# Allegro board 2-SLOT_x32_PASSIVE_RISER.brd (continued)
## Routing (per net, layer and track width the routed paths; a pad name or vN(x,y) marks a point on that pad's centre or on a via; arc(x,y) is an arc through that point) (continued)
GND_K:
  vias: v1(-8.51,332.86) v1(-8.51,322.72) v1(-7.51,332.86) v1(-7.51,322.72) v1(-6.51,332.86) v1(-6.51,322.72) v1(-5.52,332.86) v1(-5.52,322.72) v1(-4.52,332.86) v1(-4.52,322.72) v1(-3.52,332.86) v1(-3.52,322.72) v1(-2.52,332.86) v1(-2.52,327.79) v1(-2.52,322.72) v1(-1.52,332.86) v1(-1.52,327.79) v1(-1.52,322.72) v1(2.8,332.86) v1(2.8,327.79) v1(2.8,322.72) v1(3.79,332.86) v1(3.79,327.79) v1(3.79,322.72) v1(4.79,332.86) v1(4.79,327.79) v1(4.79,322.72) v1(5.79,332.86) v1(5.79,327.79) v1(5.79,322.72) v1(6.79,332.86) v1(6.79,327.79) v1(6.79,322.72) v1(7.79,332.86) v1(7.79,327.79) v1(7.79,322.72) v1(8.79,332.86) v1(8.79,327.79) v1(8.79,322.72) v1(9.78,332.86) v1(9.78,327.79) v1(9.78,322.72) v1(10.78,332.86) v1(10.78,327.79) v1(10.78,322.72) v1(11.78,332.86) v1(11.78,327.79) v1(11.78,322.72) v1(12.78,332.86) v1(12.78,327.79) v1(12.78,322.72) v1(13.78,332.86) v1(13.78,327.79) v1(13.78,322.72) v1(14.77,332.86) v1(14.77,327.79) v1(14.77,322.72) v1(15.77,332.86) v1(15.77,327.79) v1(15.77,322.72) v1(16.77,332.86) v1(16.77,327.79) v1(16.77,322.72) v1(17.77,332.86) v1(17.77,327.79) v1(17.77,322.72) v1(18.77,332.86) v1(18.77,327.79) v1(18.77,322.72) v1(19.77,332.86) v1(19.77,327.79) v1(19.77,322.72) v1(20.76,332.86) v1(20.76,327.79) v1(20.76,322.72) v1(21.76,332.86) v1(21.76,327.79) v1(21.76,322.72) v1(22.76,332.86) v1(22.76,327.79) v1(22.76,322.72) v1(23.76,332.86) v1(23.76,327.79) v1(23.76,322.72) v1(24.76,332.86) v1(24.76,327.79) v1(24.76,322.72) v1(25.76,332.86) v1(25.76,327.79) v1(25.76,322.72) v1(26.75,332.86) v1(26.75,327.79) v1(26.75,322.72) v1(27.75,332.86) v1(27.75,327.79) v1(27.75,322.72) v1(28.75,332.86) v1(28.75,327.79) v1(28.75,322.72) v1(29.75,332.86) v1(29.75,327.79) v1(29.75,322.72) v1(30.75,332.86) v1(30.75,327.79) v1(30.75,322.72) v1(31.74,332.86) v1(31.74,327.79) v1(31.74,322.72) v1(32.74,332.86) v1(32.74,327.79) v1(32.74,322.72) v1(33.74,332.86) v1(33.74,327.79) v1(33.74,322.72) v1(34.74,332.86) v1(34.74,327.79) v1(34.74,322.72) v1(35.74,332.86) v1(35.74,327.79) v1(35.74,322.72) v1(36.74,332.86) v1(36.74,327.79) v1(36.74,322.72) v1(37.73,332.86) v1(37.73,327.79) v1(37.73,322.72) v1(38.73,332.86) v1(38.73,327.79) v1(38.73,322.72) v1(39.73,332.86) v1(39.73,327.79) v1(39.73,322.72) v1(40.73,332.86) v1(40.73,327.79) v1(40.73,322.72) v1(41.73,332.86) v1(41.73,327.79) v1(41.73,322.72) v1(42.73,332.86) v1(42.73,327.79) v1(42.73,322.72) v1(43.72,332.86) v1(43.72,327.79) v1(43.72,322.72) v1(44.72,332.86) v1(44.72,327.79) v1(44.72,322.72) v1(45.72,332.86) v1(45.72,327.79) v1(45.72,322.72) v1(46.72,332.86) v1(46.72,327.79) v1(46.72,322.72) v1(47.72,332.86) v1(47.72,327.79) v1(47.72,322.72) v1(48.71,332.86) v1(48.71,327.79) v1(48.71,322.72) v1(49.71,332.86) v1(49.71,327.79) v1(49.71,322.72) v1(50.71,332.86) v1(50.71,327.79) v1(50.71,322.72) v1(51.71,332.86) v1(51.71,327.79) v1(51.71,322.72) v1(52.71,332.86) v1(52.71,327.79) v1(52.71,322.72) v1(57.41,332.86) v1(57.41,327.79) v1(57.41,322.72) v1(58.4,332.86) v1(58.4,327.79) v1(58.4,322.72) v1(63.01,332.86) v1(63.01,327.79) v1(63.01,322.72) v1(64.01,332.86) v1(64.01,327.79) v1(64.01,322.72) v1(65.01,332.86) v1(65.01,327.79) v1(65.01,322.72) v1(66.01,332.86) v1(66.01,327.79) v1(66.01,322.72) v1(67.01,332.86) v1(67.01,327.79) v1(67.01,322.72) v1(68,332.86) v1(68,327.79) v1(68,322.72) v1(69,332.86) v1(69,327.79) v1(69,322.72) v1(70,332.86) v1(70,327.79) v1(70,322.72) v1(71,332.86) v1(71,327.79) v1(71,322.72) v1(72,332.86) v1(72,327.79) v1(72,322.72) v1(73,332.86) v1(73,327.79) v1(73,322.72) v1(73.99,332.86) v1(73.99,327.79) v1(73.99,322.72) v1(74.99,332.86) v1(74.99,327.79) v1(74.99,322.72) v1(75.99,332.86) v1(75.99,327.79) v1(75.99,322.72) v1(76.99,332.86) v1(76.99,327.79) v1(76.99,322.72) v1(77.99,332.86) v1(77.99,327.79) v1(77.99,322.72) v1(78.98,332.86) v1(78.98,327.79) v1(78.98,322.72) v1(79.98,332.86) v1(79.98,327.79) v1(79.98,322.72) v1(80.98,332.86) v1(80.98,327.79) v1(80.98,322.72) v1(81.98,332.86) v1(81.98,327.79) v1(81.98,322.72) v1(82.98,332.86) v1(82.98,327.79) v1(82.98,322.72) v1(83.98,332.86) v1(83.98,327.79) v1(83.98,322.72) v1(84.97,332.86) v1(84.97,327.79) v1(84.97,322.72) v1(85.97,332.86) v1(85.97,327.79) v1(85.97,322.72) v1(86.97,332.86) v1(86.97,327.79) v1(86.97,322.72) v1(87.97,332.86) v1(87.97,327.79) v1(87.97,322.72) v1(88.97,332.86) v1(88.97,327.79) v1(88.97,322.72) v1(89.97,332.86) v1(89.97,327.79) v1(89.97,322.72) v1(90.96,332.86) v1(90.96,327.79) v1(90.96,322.72) v1(91.96,332.86) v1(91.96,327.79) v1(91.96,322.72) v1(92.96,332.86) v1(92.96,327.79) v1(92.96,322.72) v1(93.96,332.86) v1(93.96,327.79) v1(93.96,322.72) v1(94.96,332.86) v1(94.96,327.79) v1(94.96,322.72) v1(95.95,332.86) v1(95.95,327.79) v1(95.95,322.72) v1(96.95,332.86) v1(96.95,327.79) v1(96.95,322.72) v1(97.95,332.86) v1(97.95,327.79) v1(97.95,322.72) v1(98.95,332.86) v1(98.95,327.79) v1(98.95,322.72) v1(99.95,332.86) v1(99.95,327.79) v1(99.95,322.72) v1(100.95,332.86) v1(100.95,327.79) v1(100.95,322.72) v1(101.94,332.86) v1(101.94,327.79) v1(101.94,322.72) v1(102.94,332.86) v1(102.94,327.79) v1(102.94,322.72) v1(103.94,332.86) v1(103.94,327.79) v1(103.94,322.72) v1(104.94,332.86) v1(104.94,327.79) v1(104.94,322.72) v1(105.94,332.86) v1(105.94,327.79) v1(105.94,322.72) v1(106.94,332.86) v1(106.94,327.79) v1(106.94,322.72) v1(107.93,332.86) v1(107.93,327.79) v1(107.93,322.72) v1(108.93,332.86) v1(108.93,327.79) v1(108.93,322.72) v1(109.93,332.86) v1(109.93,327.79) v1(109.93,322.72) v1(110.93,332.86) v1(110.93,327.79) v1(110.93,322.72) v1(111.93,332.86) v1(111.93,327.79) v1(111.93,322.72) v1(112.92,332.86) v1(112.92,327.79) v1(112.92,322.72) v1(113.92,332.86) v1(113.92,327.79) v1(113.92,322.72) v1(114.92,332.86) v1(114.92,327.79) v1(114.92,322.72) v1(115.92,332.86) v1(115.92,327.79) v1(115.92,322.72) v1(116.92,332.86) v1(116.92,327.79) v1(116.92,322.72) v1(117.92,332.86) v1(117.92,327.79) v1(117.92,322.72) v1(118.91,332.86) v1(118.91,327.79) v1(118.91,322.72) v1(119.91,332.86) v1(119.91,327.79) v1(119.91,322.72) v1(120.91,332.86) v1(120.91,327.79) v1(120.91,322.72) v1(121.91,332.86) v1(121.91,327.79) v1(121.91,322.72) v1(122.91,332.86) v1(122.91,327.79) v1(122.91,322.72) v1(123.9,332.86) v1(123.9,327.79) v1(123.9,322.72) v1(124.9,332.86) v1(124.9,327.79) v1(124.9,322.72) v1(125.9,332.86) v1(125.9,327.79) v1(125.9,322.72) v1(126.9,332.86) v1(126.9,327.79) v1(126.9,322.72) v1(127.9,332.86) v1(127.9,327.79) v1(127.9,322.72) v1(128.9,332.86) v1(128.9,327.79) v1(128.9,322.72) v1(129.89,332.86) v1(129.89,327.79) v1(129.89,322.72) v1(130.89,332.86) v1(130.89,327.79) v1(130.89,322.72) v1(131.89,332.86) v1(131.89,327.79) v1(131.89,322.72) v1(132.89,332.86) v1(132.89,327.79) v1(132.89,322.72) v1(133.89,332.86) v1(133.89,327.79) v1(133.89,322.72) v1(134.89,332.86) v1(134.89,327.79) v1(134.89,322.72) v1(135.88,332.86) v1(135.88,327.79) v1(135.88,322.72) v1(136.88,332.86) v1(136.88,327.79) v1(136.88,322.72) v1(137.88,332.86) v1(137.88,327.79) v1(137.88,322.72) v1(138.88,332.86) v1(138.88,327.79) v1(138.88,322.72) v1(139.88,332.86) v1(139.88,327.79) v1(139.88,322.72) v1(140.87,332.86) v1(140.87,327.79) v1(140.87,322.72) v1(141.87,332.86) v1(141.87,327.79) v1(141.87,322.72) v1(142.87,332.86) v1(142.87,327.79) v1(142.87,322.72) v1(143.87,332.86) v1(143.87,327.79) v1(143.87,322.72) v1(144.87,332.86) v1(144.87,327.79) v1(144.87,322.72) v1(145.87,332.86) v1(145.87,327.79) v1(145.87,322.72) v1(146.86,332.86) v1(146.86,327.79) v1(146.86,322.72) v1(147.86,332.86) v1(147.86,327.79) v1(147.86,322.72) v1(148.86,332.86) v1(148.86,327.79) v1(148.86,322.72) v1(149.86,332.86) v1(149.86,327.79) v1(149.86,322.72) v1(150.86,332.86) v1(150.86,327.79) v1(150.86,322.72) v1(151.85,332.86) v1(151.85,327.79) v1(151.85,322.72) v1(152.85,332.86) v1(152.85,327.79) v1(152.85,322.72) v1(153.85,332.86) v1(153.85,327.79) v1(153.85,322.72) v1(154.85,332.86) v1(154.85,327.79) v1(154.85,322.72) v1(155.85,332.86) v1(155.85,327.79) v1(155.85,322.72) v1(156.85,332.86) v1(156.85,327.79) v1(156.85,322.72) v1(157.84,332.86) v1(157.84,327.79) v1(157.84,322.72) v1(158.84,332.86) v1(158.84,327.79) v1(158.84,322.72) v1(159.84,332.86) v1(159.84,327.79) v1(159.84,322.72) v1(160.84,332.86) v1(160.84,327.79) v1(160.84,322.72) v1(161.84,332.86) v1(161.84,327.79) v1(161.84,322.72) v1(162.84,332.86) v1(162.84,327.79) v1(162.84,322.72) v1(163.83,332.86) v1(163.83,327.79) v1(163.83,322.72) v1(164.83,332.86) v1(164.83,327.79) v1(164.83,322.72) v1(165.83,332.86) v1(165.83,327.79) v1(165.83,322.72) v1(166.83,332.86) v1(166.83,327.79) v1(166.83,322.72) v1(167.83,332.86) v1(167.83,327.79) v1(167.83,322.72) v1(168.82,332.86) v1(168.82,327.79) v1(168.82,322.72) v1(169.82,332.86) v1(169.82,327.79) v1(169.82,322.72) v1(170.82,332.86) v1(170.82,327.79) v1(170.82,322.72) v1(171.82,332.86) v1(171.82,327.79) v1(171.82,322.72) v1(172.82,332.86) v1(172.82,327.79) v1(172.82,322.72) v1(173.82,332.86) v1(173.82,327.79) v1(173.82,322.72) v1(174.81,332.86) v1(174.81,327.79) v1(174.81,322.72) v1(175.81,332.86) v1(175.81,327.79) v1(175.81,322.72) v1(176.81,332.86) v1(176.81,327.79) v1(176.81,322.72) v1(177.81,332.86) v1(177.81,327.79) v1(177.81,322.72) v1(178.81,332.86) v1(178.81,327.79) v1(178.81,322.72) v1(179.81,332.86) v1(179.81,327.79) v1(179.81,322.72) v1(180.8,332.86) v1(180.8,327.79) v1(180.8,322.72) v1(181.8,332.86) v1(181.8,327.79) v1(181.8,322.72) v1(182.8,332.86) v1(182.8,327.79) v1(182.8,322.72) v1(183.8,332.86) v1(183.8,327.79) v1(183.8,322.72) v1(184.8,332.86) v1(184.8,327.79) v1(184.8,322.72) v1(185.79,332.86) v1(185.79,327.79) v1(185.79,322.72) v1(186.79,332.86) v1(186.79,327.79) v1(186.79,322.72) v1(187.79,332.86) v1(187.79,327.79) v1(187.79,322.72) v1(192.53,332.86) v1(192.53,327.79) v1(192.53,322.72) v1(193.53,332.86) v1(193.53,327.79) v1(193.53,322.72) v1(194.52,332.86) v1(194.52,322.72) v1(195.52,332.86) v1(195.52,322.72) v1(196.52,332.86) v1(196.52,322.72) v1(197.52,332.86) v1(197.52,322.72) v1(198.52,332.86) v1(198.52,322.72)
P3V3: length 48.2
  TOP w0.305: 115.84,15.79 J3.A9 ; J3.A9 116.56,16.52 ; J3.A9 115.84,17.24 ; 118.49,26.77 C6.1 ; C6.1 118.06,27.15 ; C6.1 118.92,27.15 ; 119.51,26.77 C7.1 ; C7.1 119.07,27.15 ; C7.1 119.94,27.15 ; 117.04,27.15 C5.1 ; C5.1 117.91,27.15 ; C5.1 117.47,26.77 ; 116.84,20.29 J3.B8 ; J3.B8 116.12,21.02 ; J3.B8 116.84,21.74 ; J3.B8 117.56,21.02
  TOP w0.406: 106.17,23.23 105.32,23.23 104.37,24.18 R101.2 ; R45.2 v1(114.15,12.29) ; R100.2 v1(107.92,23.98) ; R48.2 v1(114.15,9.5) ; R46.2 v1(116.18,9.5) ; R99.2 v1(105.16,10.29)
  TOP w0.508: v1(112.53,7.11) v1(112.53,6.1) v1(112.53,5.08) ; v1(111.73,5.08) v1(111.73,6.1) v1(111.73,7.11) ; J3.A10 115.29,15.2 ; Q4.1 v1(106.63,27.28) ; Q3.1 v1(110.19,27.28)
  L3 w0.305: J3.A9 115.84,17.24 ; J3.A9 116.56,16.52 ; J3.A9 115.84,15.79 ; 114.84,13.79 J3.A10 ; J3.A10 115.56,14.52 ; J3.A10 114.11,14.52 ; 116.12,21.02 J3.B8 ; J3.B8 116.84,20.29 ; J3.B8 116.84,21.74
  L3 w0.508: v1(116.18,9.5) v1(114.15,9.5)
  L6 w0.305: 114.84,13.79 J3.A10 ; J3.A10 114.11,14.52 ; J3.A10 114.84,15.24 ; J3.A10 115.56,14.52 ; 115.84,15.79 J3.A9 ; J3.A9 116.56,16.52 ; J3.A9 115.84,17.24 ; J3.A9 115.12,16.52 ; J3.B8 116.84,21.74 ; J3.B8 117.56,21.02 ; J3.B8 116.12,21.02 ; J3.B8 116.84,20.29
  BOTTOM w0.508: J1.23 111.33,4.27 111.73,4.67 v1(111.73,5.08) v1(111.73,6.1) v1(111.73,7.11) ; J1.21 112.13,4.05 112.53,4.45 v1(112.53,5.08) v1(112.53,6.1) v1(112.53,7.11)
  vias: v1(110.46,12.42) v1(113.73,27.18) v1(114.62,27.18) v1(115.63,27.18) v1(116.52,27.18) v1(117.47,26.54) v1(118.49,26.54) v1(119.51,26.54)
P3V3_B: length 49.6
  TOP w0.254: R42.2 v1(116.84,32.13) ; R39.2 v1(117.86,32.13) ; R40.2 v1(118.87,32.13)
  TOP w0.305: 119.07,47.47 C25.1 ; C25.1 119.51,47.09 ; C25.1 119.94,47.47 ; C26.1 117.91,47.47 ; C26.1 117.47,47.09 ; C26.1 117.04,47.47 ; C27.1 118.92,47.47 ; C27.1 118.49,47.09 ; C27.1 118.06,47.47 ; 116.84,40.61 J4.B8 ; J4.B8 116.84,42.06 ; J4.B8 117.56,41.34 ; J4.B8 116.12,41.34 ; 115.84,36.11 J4.A9 ; J4.A9 115.84,37.56 ; J4.A9 116.56,36.84 ; 29.07,79.2 J13.4 ; J13.4 28.17,80.1 ; J13.4 29.98,80.1 ; J13.4 29.07,81
  TOP w0.406: R98.2 102.23,8.38 102.62,8 v1(103.89,8) ; U7.5 C33.1 v1(108.84,33.33) ; R103.2 v1(107.92,44.3) ; R102.2 v1(104.37,44.3)
  TOP w0.508: J4.A10 115.57,35.31 ; Q2.1 v1(110.19,47.6) ; Q1.1 v1(106.63,47.6)
  L3 w0.305: J4.A10 115.56,34.84 ; J4.A10 114.84,34.11 ; J4.A10 114.11,34.84 ; J4.A10 114.84,35.56 ; 115.12,36.84 J4.A9 ; J4.A9 115.84,36.11 ; J4.A9 115.84,37.56 ; J4.A9 116.56,36.84 ; J4.B8 116.84,42.06 ; J4.B8 116.12,41.34 ; J4.B8 116.84,40.61 ; 29.07,79.2 J13.4 ; J13.4 28.17,80.1 ; J13.4 29.98,80.1 ; J13.4 29.07,81
  L6 w0.305: 114.11,34.84 J4.A10 ; J4.A10 114.84,35.56 ; J4.A10 114.84,34.11 ; J4.A10 115.56,34.84 ; 115.84,36.11 J4.A9 ; J4.A9 115.12,36.84 ; J4.A9 115.84,37.56 ; J4.A9 116.56,36.84 ; J13.4 29.07,81 ; J13.4 28.17,80.1 ; J13.4 29.98,80.1 ; J13.4 29.07,79.2 ; 116.84,40.61 J4.B8 ; J4.B8 117.56,41.34 ; J4.B8 116.12,41.34 ; J4.B8 116.84,42.06
  BOTTOM w0.305: J13.4 29.98,80.1 ; J13.4 29.07,81 ; J13.4 28.17,80.1 ; J13.4 29.07,79.2
  vias: v1(31.11,81.2) v1(31.11,80.19) v1(31.11,79.17) v1(32.13,81.2) v1(32.13,80.19) v1(32.13,79.17) v1(113.73,47.5) v1(114.62,47.5) v1(115.63,47.5) v1(116.52,47.5) v1(117.47,46.86) v1(118.49,46.86) v1(119.51,46.86)
P3V3_STBY: length 66.8
  TOP w0.254: R71.2 93.73,44.4 93.85,44.27 v1(94.74,44.27) R72.2 ; R13.2 v1(82.93,59.82) ; R64.2 89.15,59.69 89.28,59.82 v1(90.17,59.82) R63.2 ; R108.2 93.22,62.48 93.34,62.61 v1(94.23,62.61) R109.2 ; R65.2 v1(88.14,59.82) 87.25,59.82 87.12,59.69 R66.2 ; R24.2 107.09,9.69 107.04,9.64 v1(107.04,9.59) ; R22.2 v1(101.6,50.36) ; R23.2 v1(101.6,51.37) ; R105.2 v1(87.25,25.4) 87.25,25.03 R104.2 ; R69.2 89.66,44.4 89.79,44.27 v1(90.68,44.27) R70.2 ; R110.2 91.69,44.4 91.82,44.27 v1(92.71,44.27) R111.2 ; R11.2 v1(99.31,59.82) ; R25.2 v1(107.04,12.26) ; R67.2 87.63,44.4 87.76,44.27 v1(88.65,44.27) R68.2 ; 77.34,26.14 U4.1 ; R17.2 v1(81.28,44.27) ; R106.2 91.19,62.48 91.31,62.61 v1(92.2,62.61) R107.2 ; R2.2 v1(96.77,44.27) ; R112.2 v1(95.25,59.82) ; R6.2 v1(97.28,59.82) ; R9.2 v1(80.9,59.82) ; R4.2 v1(78.87,59.82)
  TOP w0.406: U5.8 83.06,47.5 83.31,47.24 C15.1 v1(83.97,45.75) ; v1(76.1,25.22) C17.1 76.56,25.88 76.81,26.14 77.34,26.14 ; U1.5 C14.1 v1(103.9,9.64) ; v1(98.45,45.75) C16.1 97.79,46.23 96.29,47.73 U2.24 ; v1(105.03,11.43) R74.1
  TOP w0.508: v1(110.13,6.1) v1(110.93,6.1) v1(110.93,5.08)
  L3 w0.508: v1(107.04,9.59) 107.04,8.79 107.82,8 109.22,8 110.13,7.09 v1(110.13,6.1)
  BOTTOM w0.305: J4.B10 114.84,42.06 ; J4.B10 114.84,40.61 ; J4.B10 114.11,41.34 ; J4.B10 115.56,41.34 ; 114.84,20.29 J3.B10 ; J3.B10 114.84,21.74 ; J3.B10 115.56,21.02 ; J3.B10 114.11,21.02
  BOTTOM w0.508: J1.25 110.53,4.48 110.93,4.88 v1(110.93,5.08) v1(110.93,6.1) v1(110.13,6.1) ; 107.04,11.43 v1(105.03,11.43) 103.9,10.3 v1(103.9,9.64) ; 107.04,11.43 v1(107.04,12.26) ; 107.04,11.43 v1(107.04,9.59)
  vias: v1(111.95,46.28) v1(111.95,25.96) v1(112.84,46.28) v1(112.84,25.96)
P12V: length 94.4
  TOP w0.305: 122.12,21.02 J3.B2 ; J3.B2 122.84,21.74 ; J3.B2 123.56,21.02 ; J3.B2 122.84,20.29 ; J3.A2 122.84,15.24 ; J3.A2 123.56,14.52 ; J3.A2 122.12,14.52 ; J3.A2 122.84,13.79 ; 121.84,15.79 J3.A3 ; J3.A3 121.12,16.52 ; J3.A3 122.56,16.52 ; J3.A3 121.84,17.24 ; 126.75,26.19 C9.1 ; C9.1 127.31,26.72 ; C9.1 126.19,26.72 ; 122.63,26.72 C2.1 ; C2.1 123.75,26.72 ; C2.1 123.19,26.19 ; J3.B1 124.56,19.02 ; J3.B1 123.84,19.74 ; J3.B1 123.12,19.02 ; J3.B1 123.84,18.29 ; 124.41,26.72 C8.1 ; C8.1 124.97,26.19 ; C8.1 125.53,26.72 ; C1.1 121.97,26.72 ; C1.1 121.41,26.19 ; C1.1 120.85,26.72 ; J3.B3 122.56,19.02 ; J3.B3 121.12,19.02 ; J3.B3 121.84,18.29 ; J3.B3 121.84,19.74
  TOP w0.508: v1(120.13,6.1) v1(120.13,5.08) J1.1 ; v1(118.53,6.1) v1(118.53,5.08) J1.5 ; v1(119.33,6.1) v1(119.33,5.08) J1.3 ; v1(116.13,6.1) v1(116.13,5.08) J1.11 ; J1.9 v1(116.93,5.08) v1(116.93,6.1) ; v1(117.73,6.1) v1(117.73,5.08) J1.7
  L6 w0.305: 122.84,20.29 J3.B2 ; J3.B2 123.56,21.02 ; J3.B2 122.12,21.02 ; J3.B2 122.84,21.74 ; 123.12,19.02 J3.B1 ; J3.B1 123.84,19.74 ; J3.B1 124.56,19.02 ; J3.B1 123.84,18.29 ; J3.A2 123.56,14.52 ; J3.A2 122.84,13.79 ; J3.A2 122.12,14.52 ; J3.A2 122.84,15.24 ; J3.B3 121.84,19.74 ; J3.B3 122.56,19.02 ; J3.B3 121.84,18.29 ; J3.B3 121.12,19.02 ; 121.12,16.52 J3.A3 ; J3.A3 122.56,16.52 ; J3.A3 121.84,17.24 ; J3.A3 121.84,15.79
  BOTTOM w0.305: 122.12,21.02 J3.B2 ; J3.B2 122.84,21.74 ; J3.B2 123.56,21.02 ; J3.B2 122.84,20.29 ; 121.12,19.02 J3.B3 ; J3.B3 121.84,19.74 ; J3.B3 121.84,18.29 ; J3.B3 122.56,19.02 ; J3.A3 121.84,17.24 ; J3.A3 121.84,15.79 ; J3.A3 121.12,16.52 ; J3.A3 122.56,16.52 ; J3.B1 123.84,19.74 ; J3.B1 123.12,19.02 ; J3.B1 124.56,19.02 ; J3.B1 123.84,18.29 ; J3.A2 122.84,15.24 ; J3.A2 122.12,14.52 ; J3.A2 122.84,13.79 ; J3.A2 123.56,14.52
  BOTTOM w0.508: J1.5 v1(118.53,5.08) v1(118.53,6.1) ; v1(120.13,6.1) v1(120.13,5.08) J1.1 ; v1(116.93,6.1) v1(116.93,5.08) J1.9 ; J1.11 v1(116.13,5.08) v1(116.13,6.1) ; J1.7 v1(117.73,5.08) v1(117.73,6.1) ; v1(119.33,6.1) v1(119.33,5.08) J1.3
  vias: v1(121.41,25.96) v1(123.19,25.96) v1(124.97,25.96) v1(126.75,25.96) v1(128.33,27.29) v1(129.48,27.29) v1(131.25,27.29) v1(132.4,27.29) v1(134.24,27.3) v1(135,27.3) v1(135.76,27.3) v1(137.79,27.3) v1(138.56,27.3) v1(139.32,27.3)
P12V_B: length 79
  TOP w0.305: C29.1 123.75,47.04 ; C29.1 122.63,47.04 ; C29.1 123.19,46.51 ; J4.B3 122.56,39.34 ; J4.B3 121.84,38.61 ; J4.B3 121.84,40.06 ; J4.B3 121.12,39.34 ; 121.12,36.84 J4.A3 ; J4.A3 121.84,37.56 ; J4.A3 122.56,36.84 ; J4.A3 121.84,36.11 ; J4.B1 124.56,39.34 ; J4.B1 123.84,38.61 ; J4.B1 123.84,40.06 ; J4.B1 123.12,39.34 ; J4.B2 122.84,42.06 ; J4.B2 122.12,41.34 ; J4.B2 122.84,40.61 ; J4.B2 123.56,41.34 ; 120.85,47.04 C21.1 ; C21.1 121.41,46.51 ; C21.1 121.97,47.04 ; C28.1 125.53,47.04 ; C28.1 124.97,46.51 ; C28.1 124.41,47.04 ; 28.17,83.1 J13.2 ; J13.2 29.07,82.2 ; J13.2 29.07,84 ; J13.2 29.98,83.1 ; J4.A2 123.56,34.84 ; J4.A2 122.84,34.11 ; J4.A2 122.84,35.56 ; J4.A2 122.12,34.84 ; 126.75,46.51 C22.1 ; C22.1 126.19,47.04 ; C22.1 127.31,47.04
  L3 w0.305: 122.84,34.11 J4.A2 ; J4.A2 122.84,35.56 ; J4.A2 123.56,34.84 ; J4.A2 122.12,34.84 ; J4.B1 123.84,40.06 ; J4.B1 124.56,39.34 ; J4.B1 123.12,39.34 ; J4.B1 123.84,38.61 ; J4.B3 121.84,40.06 ; J4.B3 121.12,39.34 ; J4.B3 121.84,38.61 ; J4.B3 122.56,39.34 ; 122.12,41.34 J4.B2 ; J4.B2 122.84,42.06 ; J4.B2 122.84,40.61 ; J4.B2 123.56,41.34 ; J13.2 29.98,83.1 ; J13.2 29.07,82.2 ; J13.2 29.07,84 ; J13.2 28.17,83.1 ; 121.12,36.84 J4.A3 ; J4.A3 122.56,36.84 ; J4.A3 121.84,37.56 ; J4.A3 121.84,36.11
  L6 w0.305: J4.A2 123.56,34.84 ; J4.A2 122.12,34.84 ; J4.A2 122.84,35.56 ; J4.A2 122.84,34.11 ; 123.84,38.61 J4.B1 ; J4.B1 123.84,40.06 ; J4.B1 123.12,39.34 ; J4.B1 124.56,39.34 ; 121.12,36.84 J4.A3 ; J4.A3 122.56,36.84 ; J4.A3 121.84,37.56 ; J4.A3 121.84,36.11 ; J4.B3 122.56,39.34 ; J4.B3 121.12,39.34 ; J4.B3 121.84,38.61 ; J4.B3 121.84,40.06 ; J4.B2 123.56,41.34 ; J4.B2 122.84,42.06 ; J4.B2 122.84,40.61 ; J4.B2 122.12,41.34 ; J13.2 29.07,84 ; J13.2 29.98,83.1 ; J13.2 28.17,83.1 ; J13.2 29.07,82.2
  BOTTOM w0.305: J4.B3 121.84,40.06 ; J4.B3 122.56,39.34 ; J4.B3 121.12,39.34 ; J4.B3 121.84,38.61 ; 122.84,40.61 J4.B2 ; J4.B2 122.12,41.34 ; J4.B2 123.56,41.34 ; J4.B2 122.84,42.06 ; 28.17,83.1 J13.2 ; J13.2 29.98,83.1 ; J13.2 29.07,84 ; J13.2 29.07,82.2 ; 121.84,36.11 J4.A3 ; J4.A3 121.84,37.56 ; J4.A3 121.12,36.84 ; J4.A3 122.56,36.84 ; 122.12,34.84 J4.A2 ; J4.A2 122.84,34.11 ; J4.A2 122.84,35.56 ; J4.A2 123.56,34.84 ; J4.B1 123.84,40.06 ; J4.B1 123.84,38.61 ; J4.B1 124.56,39.34 ; J4.B1 123.12,39.34
  vias: v1(31.11,84.2) v1(31.11,83.19) v1(31.11,82.17) v1(32.13,84.2) v1(32.13,83.19) v1(32.13,82.17) v1(121.41,46.28) v1(123.19,46.28) v1(124.97,46.28) v1(126.75,46.28) v1(128.33,47.49) v1(129.48,47.49) v1(131.25,47.49) v1(132.4,47.49) v1(134.24,47.5) v1(135,47.5) v1(135.76,47.5) v1(137.79,47.5) v1(138.56,47.5) v1(139.32,47.5)
ALERT_N: length 3.5
  TOP w0.114: U4.8 84.92,25.14 v1(85.22,24.84) 85.65,24.84 85.83,25.02 R105.1
CLK_100M_BUF_SLOT4A_DN: length 15.8
  BOTTOM w0.13: J1.35 106.53,3.99 106.78,4.24 106.78,4.73 106.45,5.05 106.45,5.79 106.72,7.15 107.02,7.45 107.02,7.7 107.29,7.97 107.54,7.97 107.81,8.25 107.81,8.49 108.09,8.77 108.34,8.77 108.65,9.08 108.76,9.63 108.76,12.26 108.94,13.19 109.59,13.84 109.69,14.31 109.69,15.12 109.52,15.29 109.4,15.35 109.23,15.29 J3.A14
CLK_100M_BUF_SLOT4A_DP: length 15.8
  BOTTOM w0.13: J3.A13 109.48,15.8 109.54,15.62 109.7,15.54 109.99,15.25 109.99,14.28 109.88,13.69 109.22,13.04 109.06,12.23 109.06,9.6 108.93,8.93 107,7 106.75,5.76 106.75,5.18 107.08,4.85 107.08,4.24 107.33,3.99 J1.33
CLK_100M_BUF_SLOT4B_DN: length 47
  TOP w0.13: J1.38 105.73,3.99 105.98,4.24 105.98,4.92 105.8,5.09 105.8,5.48 105.98,5.66 105.98,6.34 105.82,6.49 105.47,6.49 105.33,6.35 v1(105.33,5.97)
  L6 w0.135: v1(105.33,5.97) 104.96,6.34 103.61,6.34 102.65,6.53 101.57,7.61 100.79,9.18 99.29,10.68 97.7,13.86 97.7,14.55 98.7,16.55 98.7,18.98 97.7,20.98 97.7,23.27 102.04,27.62 105.75,28.36 108.67,31.27 108.67,31.28 109.54,32.14 109.7,32.96 109.7,35.43 109.58,35.54 109.39,35.64 109.21,35.58 J4.A14
CLK_100M_BUF_SLOT4B_DP: length 47
  TOP w0.13: v1(105.33,6.99) 105.52,6.8 105.95,6.8 106.28,6.47 106.28,4.24 106.53,3.99 J1.36
  L6 w0.135: J4.A13 109.46,36.07 109.52,35.89 109.75,35.77 109.98,35.54 109.98,32.94 109.79,32 109.28,31.49 109.28,31.28 108.99,31 108.79,31 105.89,28.1 102.18,27.36 97.98,23.16 97.98,21.04 98.98,19.04 98.98,16.49 97.98,14.49 97.98,13.92 99.52,10.84 101.02,9.35 101.8,7.77 102.79,6.79 103.64,6.62 104.96,6.62 v1(105.33,6.99)
DELTA_L_85_OHMS_L1_2IN_DN: length 53.7
  TOP w0.13: J6.2 53.09,346.58 52.72,346.35 49.84,346.35 46.67,345.72 43.49,346.35 40.32,345.72 37.14,346.35 33.97,345.72 30.79,346.35 27.62,345.72 24.44,346.35 21.27,345.72 18.09,346.35 14.92,345.72 11.74,346.35 8.57,345.72 5.39,346.35 2.79,346.35 2.41,346.58 J5.1
DELTA_L_85_OHMS_L1_2IN_DP: length 53.7
  TOP w0.13: J6.1 53.09,345.83 52.72,346.05 49.87,346.05 46.67,345.41 43.49,346.04 40.32,345.41 37.14,346.04 33.97,345.41 30.79,346.04 27.62,345.41 24.44,346.04 21.27,345.41 18.09,346.04 14.92,345.41 11.74,346.04 8.57,345.41 5.36,346.05 2.79,346.05 2.41,345.83 J5.2
DELTA_L_85_OHMS_L1_5IN_DN: length 129.9
  TOP w0.13: J10.2 188.09,346.58 187.71,346.35 185.66,346.35 182.49,345.72 179.31,346.35 176.14,345.72 172.96,346.35 169.79,345.72 166.61,346.35 163.44,345.72 160.26,346.35 157.09,345.72 153.91,346.35 150.74,345.72 147.56,346.35 144.39,345.72 141.21,346.35 138.04,345.72 134.86,346.35 131.69,345.72 128.51,346.35 125.34,345.72 122.16,346.35 118.99,345.72 115.81,346.35 112.64,345.72 109.46,346.35 106.29,345.72 103.11,346.35 99.94,345.72 96.76,346.35 93.59,345.72 90.41,346.35 87.24,345.72 84.06,346.35 80.89,345.72 77.71,346.35 74.54,345.72 71.36,346.35 68.19,345.72 65.01,346.35 63.09,346.35 62.72,346.58 J9.1
DELTA_L_85_OHMS_L1_5IN_DP: length 129.9
  TOP w0.13: J10.1 188.09,345.83 187.71,346.05 185.69,346.05 182.49,345.41 179.31,346.04 176.14,345.41 172.96,346.04 169.79,345.41 166.61,346.04 163.44,345.41 160.26,346.04 157.09,345.41 153.91,346.04 150.74,345.41 147.56,346.04 144.39,345.41 141.21,346.04 138.04,345.41 134.86,346.04 131.69,345.41 128.51,346.04 125.34,345.41 122.16,346.04 118.99,345.41 115.81,346.04 112.64,345.41 109.46,346.04 106.29,345.41 103.11,346.04 99.94,345.41 96.76,346.04 93.59,345.41 90.41,346.04 87.24,345.41 84.06,346.04 80.89,345.41 77.71,346.04 74.54,345.41 71.36,346.04 68.19,345.41 64.98,346.05 63.09,346.05 62.72,345.83 J9.2
DELTA_L_85_OHMS_L3_2IN_DN: length 53.7
  L3 w0.135: v1(2.41,324.88) 2.78,325.12 5.36,325.12 8.57,324.48 11.74,325.11 14.92,324.48 18.09,325.11 21.27,324.48 24.44,325.11 27.62,324.48 30.79,325.11 33.97,324.48 37.14,325.11 40.32,324.48 43.49,325.11 46.67,324.48 49.87,325.12 52.72,325.12 v1(53.1,324.88)
  BOTTOM w0.13: J7.1 v1(2.41,324.88) ; J8.2 v1(53.1,324.88)
DELTA_L_85_OHMS_L3_2IN_DP: length 53.7
  L3 w0.135: v1(53.1,325.63) 52.72,325.4 49.84,325.4 46.67,324.76 43.49,325.4 40.32,324.76 37.14,325.4 33.97,324.76 30.79,325.4 27.62,324.76 24.44,325.4 21.27,324.76 18.09,325.4 14.92,324.76 11.74,325.4 8.57,324.76 5.39,325.4 2.78,325.4 v1(2.41,325.63)
  BOTTOM w0.13: J7.2 v1(2.41,325.63) ; J8.1 v1(53.1,325.63)
DELTA_L_85_OHMS_L3_5IN_DN: length 129.9
  L3 w0.135: v1(188.09,325.63) 187.72,325.4 185.66,325.4 182.49,324.76 179.31,325.4 176.14,324.76 172.96,325.4 169.79,324.76 166.61,325.4 163.44,324.76 160.26,325.4 157.09,324.76 153.91,325.4 150.74,324.76 147.56,325.4 144.39,324.76 141.21,325.4 138.04,324.76 134.86,325.4 131.69,324.76 128.51,325.4 125.34,324.76 122.16,325.4 118.99,324.76 115.81,325.4 112.64,324.76 109.46,325.4 106.29,324.76 103.11,325.4 99.94,324.76 96.76,325.4 93.59,324.76 90.41,325.4 87.24,324.76 84.06,325.4 80.89,324.76 77.71,325.4 74.54,324.76 71.36,325.4 68.19,324.76 65.01,325.4 63.09,325.4 v1(62.71,325.63)
  BOTTOM w0.13: J12.2 v1(62.71,325.63) ; J11.1 v1(188.09,325.63)
DELTA_L_85_OHMS_L3_5IN_DP: length 129.9
  L3 w0.135: v1(188.09,324.88) 187.71,325.12 185.69,325.12 182.49,324.48 179.31,325.11 176.14,324.48 172.96,325.11 169.79,324.48 166.61,325.11 163.44,324.48 160.26,325.11 157.09,324.48 153.91,325.11 150.74,324.48 147.56,325.11 144.39,324.48 141.21,325.11 138.04,324.48 134.86,325.11 131.69,324.48 128.51,325.11 125.34,324.48 122.16,325.11 118.99,324.48 115.81,325.11 112.64,324.48 109.46,325.11 106.29,324.48 103.11,325.11 99.94,324.48 96.76,325.11 93.59,324.48 90.41,325.11 87.24,324.48 84.06,325.11 80.89,324.48 77.71,325.11 74.54,324.48 71.36,325.11 68.19,324.48 64.98,325.12 63.09,325.12 v1(62.71,324.88)
  BOTTOM w0.13: J11.2 v1(188.09,324.88) ; J12.1 v1(62.71,324.88)
DELTA_L_85_OHMS_L6_2IN_DN: length 53.7
  TOP w0.13: J15.1 v1(53.1,329.95) ; J16.2 v1(2.41,329.95)
  L6 w0.135: v1(53.1,329.95) 52.72,330.19 49.87,330.19 46.67,329.55 43.49,330.18 40.32,329.55 37.14,330.18 33.97,329.55 30.79,330.18 27.62,329.55 24.44,330.18 21.27,329.55 18.09,330.18 14.92,329.55 11.74,330.18 8.57,329.55 5.36,330.19 2.78,330.19 v1(2.41,329.95)
DELTA_L_85_OHMS_L6_2IN_DP: length 53.7
  TOP w0.13: J16.1 v1(2.41,330.7) ; J15.2 v1(53.1,330.7)
  L6 w0.135: v1(2.41,330.7) 2.78,330.47 5.39,330.47 8.57,329.83 11.74,330.47 14.92,329.83 18.09,330.47 21.27,329.83 24.44,330.47 27.62,329.83 30.79,330.47 33.97,329.83 37.14,330.47 40.32,329.83 43.49,330.47 46.67,329.83 49.84,330.47 52.72,330.47 v1(53.1,330.7)
DELTA_L_85_OHMS_L6_5IN_DN: length 129.9
  TOP w0.13: J20.2 v1(62.71,329.95) ; J19.1 v1(188.09,329.95)
  L6 w0.135: v1(188.09,329.95) 187.71,330.19 185.69,330.19 182.49,329.55 179.31,330.18 176.14,329.55 172.96,330.18 169.79,329.55 166.61,330.18 163.44,329.55 160.26,330.18 157.09,329.55 153.91,330.18 150.74,329.55 147.56,330.18 144.39,329.55 141.21,330.18 138.04,329.55 134.86,330.18 131.69,329.55 128.51,330.18 125.34,329.55 122.16,330.18 118.99,329.55 115.81,330.18 112.64,329.55 109.46,330.18 106.29,329.55 103.11,330.18 99.94,329.55 96.76,330.18 93.59,329.55 90.41,330.18 87.24,329.55 84.06,330.18 80.89,329.55 77.71,330.18 74.54,329.55 71.36,330.18 68.19,329.55 64.98,330.19 63.09,330.19 v1(62.71,329.95)
DELTA_L_85_OHMS_L6_5IN_DP: length 129.9
  TOP w0.13: J19.2 v1(188.09,330.7) ; J20.1 v1(62.71,330.7)
  L6 w0.135: v1(188.09,330.7) 187.72,330.47 185.66,330.47 182.49,329.83 179.31,330.47 176.14,329.83 172.96,330.47 169.79,329.83 166.61,330.47 163.44,329.83 160.26,330.47 157.09,329.83 153.91,330.47 150.74,329.83 147.56,330.47 144.39,329.83 141.21,330.47 138.04,329.83 134.86,330.47 131.69,329.83 128.51,330.47 125.34,329.83 122.16,330.47 118.99,329.83 115.81,330.47 112.64,329.83 109.46,330.47 106.29,329.83 103.11,330.47 99.94,329.83 96.76,330.47 93.59,329.83 90.41,330.47 87.24,329.83 84.06,330.47 80.89,329.83 77.71,330.47 74.54,329.83 71.36,330.47 68.19,329.83 65.01,330.47 63.09,330.47 v1(62.71,330.7)
DELTA_L_85_OHMS_L8_2IN_DN: length 53.7
  BOTTOM w0.13: J17.2 2.41,341.51 2.79,341.28 5.39,341.28 8.57,340.65 11.74,341.28 14.92,340.65 18.09,341.28 21.27,340.65 24.44,341.28 27.62,340.65 30.79,341.28 33.97,340.65 37.14,341.28 40.32,340.65 43.49,341.28 46.67,340.65 49.84,341.28 52.72,341.28 53.09,341.51 J14.1
DELTA_L_85_OHMS_L8_2IN_DP: length 53.7
  BOTTOM w0.13: J17.1 2.41,340.76 2.79,340.98 5.36,340.98 8.57,340.34 11.74,340.97 14.92,340.34 18.09,340.97 21.27,340.34 24.44,340.97 27.62,340.34 30.79,340.97 33.97,340.34 37.14,340.97 40.32,340.34 43.49,340.97 46.67,340.34 49.87,340.98 52.72,340.98 53.09,340.76 J14.2
DELTA_L_85_OHMS_L8_5IN_DN: length 129.9
  BOTTOM w0.13: J18.1 62.72,340.76 63.09,340.98 64.98,340.98 68.19,340.34 71.36,340.97 74.54,340.34 77.71,340.97 80.89,340.34 84.06,340.97 87.24,340.34 90.41,340.97 93.59,340.34 96.76,340.97 99.94,340.34 103.11,340.97 106.29,340.34 109.46,340.97 112.64,340.34 115.81,340.97 118.99,340.34 122.16,340.97 125.34,340.34 128.51,340.97 131.69,340.34 134.86,340.97 138.04,340.34 141.21,340.97 144.39,340.34 147.56,340.97 150.74,340.34 153.91,340.97 157.09,340.34 160.26,340.97 163.44,340.34 166.61,340.97 169.79,340.34 172.96,340.97 176.14,340.34 179.31,340.97 182.49,340.34 185.69,340.98 187.71,340.98 188.09,340.76 J22.2
DELTA_L_85_OHMS_L8_5IN_DP: length 129.9
  BOTTOM w0.13: J18.2 62.72,341.51 63.09,341.28 65.01,341.28 68.19,340.65 71.36,341.28 74.54,340.65 77.71,341.28 80.89,340.65 84.06,341.28 87.24,340.65 90.41,341.28 93.59,340.65 96.76,341.28 99.94,340.65 103.11,341.28 106.29,340.65 109.46,341.28 112.64,340.65 115.81,341.28 118.99,340.65 122.16,341.28 125.34,340.65 128.51,341.28 131.69,340.65 134.86,341.28 138.04,340.65 141.21,341.28 144.39,340.65 147.56,341.28 150.74,340.65 153.91,341.28 157.09,340.65 160.26,341.28 163.44,340.65 166.61,341.28 169.79,340.65 172.96,341.28 176.14,340.65 179.31,341.28 182.49,340.65 185.66,341.28 187.71,341.28 188.09,341.51 J22.1
FM_SLOT4_CFG0: length 6.8
  TOP w0.114: R8.2 113.26,7.26 113.6,6.92 v1(113.6,5.97)
  BOTTOM w0.114: J1.19 112.93,3.96 113.16,4.19 113.16,5.53 v1(113.6,5.97)
FM_SLOT4_CFG1: length 8.2
  TOP w0.114: J1.18 113.73,4 114.05,4.32 114.05,7.11 113.65,7.51 113.65,9.11 v1(113.26,9.5) R14.2
FM_SLOT4_CFG2: length 7.2
  TOP w0.114: R16.2 v1(95.25,8.86)
  BOTTOM w0.114: J1.63 95.33,4.24 95.25,4.32 v1(95.25,8.86)
FM_SLOT4_CFG3: length 7.6
  TOP w0.114: R18.2 v1(92.43,8.86) 91.37,7.8 91.37,4.12 91.33,4.08 J1.66
J3_A1: length 4.3
  TOP w0.114: J3.A1 124.96,15.39 R44.2
J4_A1: length 4.4
  TOP w0.114: R38.2 125.34,35.33 J4.A1
J4_JTAG_NTRST: length 6.7
  TOP w0.114: R41.2 114.3,33.91 113.92,34.29 113.92,35.05 115.07,36.2 115.07,38.56 J4.B9
J4_JTAG_TCK: length 3.3
  TOP w0.114: R43.2 119.89,36.79 J4.A5
J4_JTAG_TDI: length 1.3
  TOP w0.114: R40.1 118.87,34.8 J4.A6
J4_JTAG_TDO: length 3.3
  TOP w0.114: R39.1 117.86,36.82 J4.A7
J4_JTAG_TMS: length 1.3
  TOP w0.114: R42.1 J4.A8
JTAG_NTRST: length 8.9
  TOP w0.114: J3.B9 115.07,18.24 115.07,16 112.45,13.38 R47.2 112.45,12.94 112.45,12.93 112.45,11.73 112.45,11.72 R58.1
JTAG_SLOT4_NTRST: length 148.6
  TOP w0.114: v1(4.72,5.97) 3.52,4.77 J2.60 ; R58.2 v1(113.26,10.9)
  L3 w0.137: v1(113.26,10.9) 113.92,11.56 116.08,11.56 116.37,11.84 117.98,13.46 117.98,14.99 119,16 119,17.02 119.51,17.53 120.27,17.53 120.9,18.16 120.9,19.3 119.89,20.32 119.89,21.59 118.07,23.4 114.03,23.4 112.99,24.44 101.67,24.44 97.66,28.45 29.34,28.45 9.27,8.38 9.24,8.38 6.85,8.38 5.97,7.49 5.97,6.6 5.33,5.97 v1(4.72,5.97)
JTAG_SLOT4_TCK: length 153.3
  TOP w0.114: J2.56 5.12,4.11 5.33,4.32 5.33,7.26 v1(4.72,7.87) ; v1(116.99,10.9) 116.31,10.9 116.18,11.02 R56.2
  L3 w0.137: v1(4.72,7.87) 6.16,9.31 8.86,9.31 25.5,25.95 25.52,25.95 28.95,29.38 98.05,29.38 102.05,25.38 113.38,25.38 114.42,24.34 118.46,24.34 119.86,22.94 122.14,22.94 124.71,20.38 124.71,18.66 122.71,16.66 122.71,16.16 122.2,15.65 120.83,15.65 120.05,14.87 120.05,14.01 116.99,10.96 v1(116.99,10.9)
JTAG_SLOT4_TDI: length 161.3
  TOP w0.114: R51.2 116.18,8.23 116.31,8.1 v1(116.99,8.1)
  L3 w0.137: v1(116.99,8.1) 117.22,8.33 117.22,9.78 120.62,13.18 123.39,13.18 125.73,15.52 125.73,20.68 122.53,23.88 120.25,23.88 118.85,25.27 114.94,25.27 113.28,26.92 111.51,26.92 111,26.42 102.34,26.42 98.44,30.32 28.54,30.32 8.47,10.25 5.32,10.25 v1(4.72,9.65)
  BOTTOM w0.114: v1(4.72,9.65) 6.44,7.93 6.44,4.35 6.72,4.07 J2.51
JTAG_SLOT4_TDO: length 151.2
  TOP w0.114: R50.2 114.15,11.02 114.27,10.9 v1(114.96,10.9)
  L3 w0.137: v1(4.72,6.99) 6.58,8.84 9.07,8.84 29.14,28.92 97.86,28.92 101.86,24.91 113.19,24.91 114.23,23.87 118.27,23.87 119.67,22.47 121.04,22.47 121.79,21.72 121.79,20.83 122.81,19.82 122.81,18.42 121.92,17.53 121.28,17.53 120.65,16.89 120.65,16.13 119.58,15.06 119.58,14.21 116.27,10.9 v1(114.96,10.9)
  BOTTOM w0.114: J2.53 5.92,4.7 5.47,5.15 5.47,6.24 v1(4.72,6.99)
JTAG_SLOT4_TMS: length 160.5
  TOP w0.114: v1(4.72,8.76) 5.92,7.56 J2.54 ; R55.2 114.15,8.23 114.27,8.1 v1(114.96,8.1)
  L3 w0.137: v1(114.96,8.1) 115.49,8.64 116.31,8.64 116.75,9.08 116.75,9.97 120.43,13.65 123.2,13.65 124.21,14.65 124.21,15.49 125.18,16.46 125.18,20.57 122.34,23.41 120.05,23.41 118.66,24.81 114.74,24.81 113.09,26.46 111.7,26.46 111.15,25.91 102.19,25.91 98.24,29.85 28.76,29.85 25.33,26.42 25.3,26.42 8.67,9.78 5.75,9.78 v1(4.72,8.76)
JTAG_TCK: length 6.4
  TOP w0.114: R56.1 R49.2 116.99,13.36 117.86,14.22 117.86,14.99 118.36,15.49 118.82,15.49 J3.A5
JTAG_TDI: length 6.7
  TOP w0.114: R51.1 R46.1 117.37,10.16 117.5,10.29 117.5,13.18 J3.A6
JTAG_TDO: length 6.3
  TOP w0.114: J3.A7 116.63,15.31 116.38,15.31 116.06,14.99 116.06,14.5 114.96,13.4 R45.1 R50.1
JTAG_TMS: length 6.8
  TOP w0.114: R55.1 R48.1 115.41,10.16 115.54,10.29 115.54,13.21 J3.A8
MUX_A0: length 5.9
  TOP w0.114: U2.1 v1(96.29,56.21) 96.29,56.79 97.16,57.66 98.04,57.66 98.3,57.91 R12.2 R11.1
MUX_A1: length 4.8
  TOP w0.114: U2.2 95.64,57.16 v1(96.27,57.78) R7.2 R6.1
MUX_A2: length 4.9
  TOP w0.114: R2.1 R3.2 95.76,46.26 v1(94.34,47.68) U2.21
PE_CPU1_1A_RX_0_DN: length 53.9
  TOP w0.13: v1(41.33,32.88) 41.69,32.53 41.69,32.38 41.56,32.26 29.38,29.82 8.61,9.05 7.77,4.88 7.77,4.24 7.52,3.99 J2.50
  BOTTOM w0.13: J4.A81 42.17,36.18 42.11,36 41.9,35.9 41.69,35.68 41.69,33.24 v1(41.33,32.88)
PE_CPU1_1A_RX_0_DP: length 53.9
  TOP w0.13: J2.48 8.32,3.99 8.08,4.24 8.08,4.85 8.89,8.9 29.53,29.54 41.71,31.98 41.99,32.26 41.99,32.53 v1(42.35,32.88)
  BOTTOM w0.13: J4.A80 42.42,35.67 42.25,35.73 42.08,35.65 41.99,35.56 41.99,34.42 42.17,34.24 42.17,33.85 41.99,33.68 41.99,33.24 v1(42.35,32.88)
PE_CPU1_1A_RX_1_DN: length 55.6
  TOP w0.13: v1(45.33,32.88) 45.7,32.51 45.7,32.19 45.29,31.78 30.44,28.81 11.09,9.46 10.17,4.88 10.17,4.24 9.92,3.99 J2.44
  BOTTOM w0.13: J4.A77 46.17,36.18 46.11,36 45.9,35.9 45.69,35.68 45.69,33.24 v1(45.33,32.88)
PE_CPU1_1A_RX_1_DP: length 55.6
  TOP w0.13: J2.42 10.72,3.99 10.48,4.24 10.48,4.85 11.37,9.31 30.59,28.53 45.44,31.5 46,32.07 46,32.54 v1(46.35,32.88)
  BOTTOM w0.13: v1(46.35,32.88) 45.99,33.24 45.99,33.68 46.17,33.85 46.17,34.24 45.99,34.42 45.99,35.56 46.08,35.65 46.25,35.73 46.42,35.67 J4.A76
PE_CPU1_1A_RX_2_DN: length 57.2
  TOP w0.13: v1(49.33,32.88) 49.69,32.52 49.69,32 48.99,31.3 31.67,27.84 13.54,9.71 12.57,4.88 12.57,4.24 12.32,3.99 J2.38
  BOTTOM w0.13: v1(49.33,32.88) 49.69,33.24 49.69,35.68 49.9,35.9 50.11,36 50.17,36.18 J4.A73
PE_CPU1_1A_RX_2_DP: length 57.2
  TOP w0.13: v1(50.35,32.88) 50,32.53 50,31.87 49.14,31.02 31.82,27.56 13.82,9.56 12.88,4.85 12.88,4.24 13.12,3.99 J2.36
  BOTTOM w0.13: J4.A72 50.42,35.67 50.25,35.73 50.08,35.65 49.99,35.56 49.99,34.42 50.17,34.24 50.17,33.85 49.99,33.68 49.99,33.24 v1(50.35,32.88)
PE_CPU1_1A_RX_3_DN: length 58.9
  TOP w0.13: J2.32 14.72,3.99 14.97,4.24 14.97,4.88 16.02,10.12 32.73,26.83 50.26,30.33 51.14,31.21 53.38,31.66 53.69,31.96 53.69,32.53 v1(53.33,32.88)
  BOTTOM w0.13: v1(53.33,32.88) 53.69,33.24 53.69,35.68 53.9,35.9 54.11,36 54.17,36.18 J4.A69
PE_CPU1_1A_RX_3_DP: length 58.9
  TOP w0.13: J2.30 15.52,3.99 15.28,4.24 15.28,4.85 16.3,9.97 32.88,26.55 50.41,30.05 51.29,30.93 53.53,31.37 53.99,31.84 53.99,32.53 v1(54.35,32.88)
  BOTTOM w0.13: v1(54.35,32.88) 53.99,33.24 53.99,33.68 54.17,33.85 54.17,34.24 53.99,34.42 53.99,35.56 54.08,35.65 54.25,35.73 54.42,35.67 J4.A68
PE_CPU1_1A_TX_0_DN: length 63.1
  L6 w0.135: J4.B79 44.21,40.07 44.39,40.13 44.39,40.13 44.52,40.06 44.7,39.88 44.7,36.39 43.7,35.39 43.7,32.96 42.97,32.23 41.5,31.93 41.33,32.05 40.93,31.97 40.82,31.8 40.42,31.72 40.25,31.83 39.85,31.75 39.74,31.58 39.34,31.5 39.17,31.62 38.78,31.54 38.66,31.37 38.27,31.29 38.1,31.4 37.7,31.32 37.59,31.15 29.03,29.44 10.96,11.37 10.75,11.37 10.47,11.08 10.47,10.88 10.18,10.59 9.98,10.59 9.69,10.31 9.69,10.1 9.41,9.81 9.2,9.81 8.92,9.53 8.92,9.32 8.63,9.04 8.19,6.84 7.97,6.62 7.49,6.62 v1(7.12,6.99)
  BOTTOM w0.13: J2.45 9.12,3.99 8.88,4.24 8.88,4.66 8.5,5.04 8.5,6.44 8.14,6.8 7.31,6.8 v1(7.12,6.99)
PE_CPU1_1A_TX_0_DP: length 63.1
  L6 w0.135: v1(7.12,5.97) 7.49,6.34 8.08,6.34 8.45,6.7 8.89,8.9 29.17,29.18 43.11,31.97 43.98,32.85 43.98,35.28 44.98,36.28 44.98,40 44.68,40.29 44.51,40.38 44.51,40.38 44.45,40.56 J4.B78
  BOTTOM w0.13: J2.47 8.32,3.99 8.57,4.24 8.57,4.53 8.19,4.92 8.19,5.3 8.02,5.47 8.02,5.86 8.19,6.04 8.19,6.31 8.01,6.49 7.27,6.49 7.12,6.35 v1(7.12,5.97)
PE_CPU1_1A_TX_1_DN: length 64.9
  L6 w0.135: J4.B75 48.21,40.07 48.39,40.13 48.39,40.13 48.52,40.06 48.7,39.88 48.7,36.39 47.7,35.39 47.7,32.58 47.07,31.94 46.7,31.87 46.52,31.98 46.13,31.9 46.02,31.73 45.62,31.65 45.45,31.77 45.05,31.69 44.94,31.52 44.54,31.44 44.37,31.55 43.98,31.47 43.86,31.3 43.47,31.22 43.3,31.34 42.9,31.26 42.79,31.09 30.24,28.58 13.44,11.78 13.24,11.78 12.95,11.49 12.95,11.28 12.66,11 12.46,11 12.17,10.71 12.17,10.51 11.89,10.22 11.68,10.22 11.4,9.94 11.4,9.73 11.11,9.45 10.59,6.84 10.37,6.62 9.89,6.62 v1(9.53,6.99)
  BOTTOM w0.13: J2.39 11.52,3.99 11.28,4.24 11.28,4.66 10.9,5.04 10.9,6.44 10.54,6.8 9.71,6.8 v1(9.53,6.99)
PE_CPU1_1A_TX_1_DP: length 64.9
  L6 w0.135: J4.B74 48.45,40.56 48.51,40.38 48.51,40.38 48.68,40.29 48.98,40 48.98,36.28 47.98,35.28 47.98,32.46 47.21,31.68 30.38,28.32 11.37,9.31 10.85,6.7 10.48,6.34 9.89,6.34 v1(9.53,5.97)
  BOTTOM w0.13: v1(9.53,5.97) 9.53,6.35 9.67,6.49 10.41,6.49 10.59,6.31 10.59,6.04 10.42,5.86 10.42,5.47 10.59,5.3 10.59,4.92 10.97,4.53 10.97,4.24 10.72,3.99 J2.41
PE_CPU1_1A_TX_2_DN: length 66.2
  L6 w0.135: v1(11.92,6.99) 12.29,6.62 12.77,6.62 12.99,6.84 13.56,9.7 13.85,9.98 13.85,10.19 14.13,10.47 14.34,10.47 14.62,10.76 14.62,10.96 14.91,11.25 15.11,11.25 15.4,11.53 15.4,11.74 15.69,12.02 15.89,12.02 31.52,27.65 45.64,30.48 45.76,30.65 46.15,30.73 46.32,30.61 46.72,30.69 46.83,30.86 47.23,30.94 47.4,30.83 47.8,30.91 47.91,31.08 48.3,31.16 48.48,31.04 48.87,31.12 48.98,31.29 49.38,31.37 49.55,31.26 49.95,31.34 51.7,33.09 51.7,35.39 52.7,36.39 52.7,39.88 52.52,40.06 52.39,40.13 52.39,40.13 52.21,40.07 J4.B71
  BOTTOM w0.13: J2.33 13.92,3.99 13.68,4.24 13.68,4.66 13.3,5.04 13.3,6.44 12.94,6.8 12.11,6.8 v1(11.92,6.99)
PE_CPU1_1A_TX_2_DP: length 66.2
  L6 w0.135: J4.B70 52.45,40.56 52.51,40.38 52.51,40.38 52.68,40.29 52.98,40 52.98,36.28 51.98,35.28 51.98,32.98 50.09,31.08 31.66,27.4 13.82,9.56 13.25,6.7 12.88,6.34 12.29,6.34 v1(11.92,5.97)
  BOTTOM w0.13: J2.35 13.12,3.99 13.37,4.24 13.37,4.53 12.99,4.92 12.99,5.3 12.82,5.47 12.82,5.86 12.99,6.04 12.99,6.31 12.81,6.49 12.07,6.49 11.92,6.35 v1(11.92,5.97)
PE_CPU1_1A_TX_3_DN: length 68.1
  L6 w0.135: v1(14.32,6.99) 14.69,6.62 15.17,6.62 15.39,6.84 16.04,10.11 16.33,10.39 16.33,10.6 16.62,10.88 16.82,10.88 17.11,11.17 17.11,11.37 17.39,11.66 17.6,11.66 17.88,11.94 17.88,12.15 18.17,12.43 18.37,12.43 32.56,26.63 47.9,29.69 48.02,29.86 48.41,29.94 48.58,29.83 48.98,29.91 49.09,30.08 49.49,30.16 49.66,30.04 50.05,30.12 51.11,31.17 52.93,31.54 53.04,31.71 53.44,31.79 53.61,31.68 54,31.75 54.12,31.93 54.51,32 54.68,31.89 55.08,31.97 55.7,32.59 55.7,35.39 56.7,36.39 56.7,39.88 56.52,40.06 56.39,40.13 56.39,40.13 56.21,40.07 J4.B67
  BOTTOM w0.13: J2.27 16.32,3.99 16.08,4.24 16.08,4.66 15.7,5.04 15.7,6.44 15.34,6.8 14.51,6.8 v1(14.32,6.99)
PE_CPU1_1A_TX_3_DP: length 68.1
  L6 w0.135: v1(14.32,5.97) 14.69,6.34 15.28,6.34 15.65,6.7 16.3,9.97 32.7,26.37 50.19,29.87 51.24,30.92 55.22,31.71 55.98,32.48 55.98,35.28 56.98,36.28 56.98,40 56.68,40.29 56.51,40.38 56.51,40.38 56.45,40.56 J4.B66
  BOTTOM w0.13: J2.29 15.52,3.99 15.77,4.24 15.77,4.53 15.39,4.92 15.39,5.3 15.22,5.47 15.22,5.86 15.39,6.04 15.39,6.31 15.21,6.49 14.47,6.49 14.32,6.35 v1(14.32,5.97)
PE_CPU1_1B_RX_4_DN: length 60.5
  TOP w0.13: v1(57.33,32.88) 57.69,32.52 57.69,32.23 57.59,31.75 56.92,31.07 51.64,30.02 50.83,29.21 33.94,25.83 18.47,10.37 17.37,4.88 17.37,4.24 17.12,3.99 J2.26
  BOTTOM w0.13: J4.A65 58.17,36.18 58.11,36 57.9,35.9 57.69,35.68 57.69,33.24 v1(57.33,32.88)
PE_CPU1_1B_RX_4_DP: length 60.5
  TOP w0.13: v1(58.35,32.88) 58,32.53 58,32.2 57.88,31.6 57.07,30.79 51.79,29.74 50.98,28.93 34.09,25.55 18.75,10.22 17.68,4.85 17.68,4.24 17.92,3.99 J2.24
  BOTTOM w0.13: J4.A64 58.42,35.67 58.25,35.73 58.08,35.65 57.99,35.56 57.99,34.42 58.17,34.24 58.17,33.85 57.99,33.68 57.99,33.24 v1(58.35,32.88)
PE_CPU1_1B_RX_5_DN: length 62.1
  TOP w0.13: J2.20 19.52,3.99 19.77,4.24 19.77,4.88 20.87,10.38 35.36,24.87 51.39,28.07 52.21,28.9 60.77,30.61 61.52,31.36 61.69,32.19 61.69,32.53 v1(61.33,32.88)
  BOTTOM w0.13: v1(61.33,32.88) 61.69,33.24 61.69,35.68 61.9,35.9 62.11,36 62.17,36.18 J4.A61
PE_CPU1_1B_RX_5_DP: length 62.1
  TOP w0.13: v1(62.35,32.88) 61.99,32.53 61.99,32.16 61.8,31.21 60.92,30.33 52.36,28.62 51.54,27.79 35.51,24.59 21.15,10.23 20.08,4.85 20.08,4.24 20.32,3.99 J2.18
  BOTTOM w0.13: J4.A60 62.42,35.67 62.25,35.73 62.08,35.65 61.99,35.56 61.99,34.42 62.17,34.24 62.17,33.85 61.99,33.68 61.99,33.24 v1(62.35,32.88)
PE_CPU1_1B_RX_6_DN: length 63.5
  TOP w0.13: v1(65.33,32.88) 65.69,32.53 65.69,32.13 65.59,31.64 63.97,30.02 52.8,27.79 51.98,26.97 36.67,23.91 23.31,10.55 22.17,4.88 22.17,4.24 21.92,3.99 J2.14
  BOTTOM w0.13: J4.A57 66.17,36.18 66.11,36 65.9,35.9 65.69,35.68 65.69,33.24 v1(65.33,32.88)
PE_CPU1_1B_RX_6_DP: length 63.5
  TOP w0.13: v1(66.35,32.88) 65.99,32.53 65.99,32.1 65.87,31.49 64.13,29.74 52.95,27.51 52.13,26.69 36.82,23.63 23.59,10.4 22.48,4.85 22.48,4.24 22.72,3.99 J2.12
  BOTTOM w0.13: v1(66.35,32.88) 65.99,33.24 65.99,33.68 66.17,33.85 66.17,34.24 65.99,34.42 65.99,35.56 66.08,35.65 66.25,35.73 66.42,35.67 J4.A56
PE_CPU1_1B_RX_7_DN: length 65
  TOP w0.13: v1(69.33,32.88) 69.7,32.52 69.7,32.18 69.59,31.66 68.86,30.93 66.07,30.38 64.63,28.93 53.38,26.68 52.56,25.86 38.08,22.97 25.72,10.6 24.57,4.88 24.57,4.24 24.32,3.99 J2.8
  BOTTOM w0.13: J4.A53 70.17,36.18 70.11,36 69.9,35.9 69.69,35.68 69.69,33.24 v1(69.33,32.88)
PE_CPU1_1B_RX_7_DP: length 65
  TOP w0.13: J2.6 25.12,3.99 24.88,4.24 24.88,4.85 26,10.45 38.23,22.69 52.71,25.58 53.53,26.4 64.78,28.65 66.22,30.09 69.01,30.65 69.87,31.51 70,32.15 70,32.53 v1(70.35,32.88)
  BOTTOM w0.13: J4.A52 70.42,35.67 70.25,35.73 70.08,35.65 69.99,35.56 69.99,34.42 70.17,34.24 70.17,33.85 69.99,33.68 69.99,33.24 v1(70.35,32.88)
PE_CPU1_1B_TX_4_DN: length 69.6
  L6 w0.135: J4.B63 60.21,40.07 60.39,40.13 60.39,40.13 60.52,40.06 60.7,39.88 60.7,38.53 60.7,37.81 60.7,36.39 59.7,35.39 59.7,32.76 58.25,31.31 57.86,31.23 57.69,31.35 57.29,31.27 57.18,31.1 56.78,31.02 56.61,31.13 56.22,31.05 56.1,30.88 55.71,30.8 55.54,30.92 55.14,30.84 55.03,30.67 54.63,30.59 54.46,30.7 54.06,30.62 53.95,30.45 51.61,29.98 50.63,29 33.77,25.63 20.82,12.68 20.62,12.68 20.33,12.4 20.33,12.19 20.05,11.91 19.84,11.91 19.56,11.62 19.56,11.42 19.27,11.13 19.07,11.13 18.78,10.85 18.78,10.64 18.49,10.36 17.79,6.84 17.57,6.62 17.09,6.62 v1(16.72,6.99)
  BOTTOM w0.13: J2.21 18.72,3.99 18.48,4.24 18.48,4.66 18.1,5.04 18.1,6.44 17.74,6.8 16.91,6.8 v1(16.72,6.99)
PE_CPU1_1B_TX_4_DP: length 69.6
  L6 w0.135: J4.B62 60.45,40.56 60.51,40.38 60.51,40.38 60.68,40.29 60.98,40 60.98,38.53 60.98,37.82 60.98,36.28 59.98,35.28 59.98,32.65 58.39,31.06 51.74,29.73 50.76,28.75 33.91,25.37 18.75,10.22 18.05,6.7 17.68,6.34 17.09,6.34 v1(16.72,5.97)
  BOTTOM w0.13: J2.23 17.92,3.99 18.17,4.24 18.17,4.53 17.79,4.92 17.79,5.3 17.62,5.47 17.62,5.86 17.79,6.04 17.79,6.31 17.61,6.49 16.87,6.49 16.72,6.35 v1(16.72,5.97)
PE_CPU1_1B_TX_5_DN: length 71
  L6 w0.135: v1(19.12,6.99) 19.49,6.62 19.97,6.62 20.19,6.84 20.9,10.37 21.18,10.66 21.18,10.86 21.47,11.15 21.67,11.15 21.96,11.43 21.96,11.64 22.24,11.92 22.45,11.92 22.73,12.21 22.73,12.41 23.02,12.7 23.22,12.7 35.2,24.67 51.18,27.87 52.18,28.87 57.31,29.89 57.42,30.06 57.82,30.14 57.99,30.03 58.39,30.11 58.5,30.28 58.9,30.36 59.07,30.24 59.46,30.32 59.58,30.49 59.97,30.57 60.14,30.46 60.54,30.54 60.65,30.71 61.05,30.79 61.22,30.67 61.61,30.75 63.7,32.84 63.7,35.39 64.7,36.39 64.7,39.87 64.51,40.06 64.38,40.12 64.38,40.12 64.2,40.06 J4.B59
  BOTTOM w0.13: v1(19.12,6.99) 19.31,6.8 20.14,6.8 20.5,6.44 20.5,5.04 20.88,4.66 20.88,4.24 21.12,3.99 J2.15
PE_CPU1_1B_TX_5_DP: length 71
  L6 w0.135: v1(19.12,5.97) 19.49,6.34 20.08,6.34 20.45,6.7 21.15,10.23 35.33,24.41 51.32,27.61 52.32,28.61 61.75,30.5 63.98,32.73 63.98,35.28 64.98,36.28 64.98,39.99 64.68,40.29 64.51,40.37 64.51,40.37 64.45,40.55 J4.B58
  BOTTOM w0.13: J2.17 20.32,3.99 20.57,4.24 20.57,4.53 20.19,4.92 20.19,5.3 20.02,5.47 20.02,5.86 20.19,6.04 20.19,6.31 20.01,6.49 19.27,6.49 19.12,6.35 v1(19.12,5.97)
PE_CPU1_1B_TX_6_DN: length 72.7
  L6 w0.135: J4.B55 68.2,40.06 68.38,40.12 68.51,40.06 68.7,39.87 68.7,36.39 67.7,35.39 67.7,32.56 66.92,31.78 65.48,31.49 65.19,31.2 64.99,31.2 64.7,30.92 64.7,30.71 64.02,30.03 63.62,29.95 63.45,30.07 63.06,29.99 62.94,29.82 62.55,29.74 62.38,29.85 61.98,29.77 61.87,29.6 61.47,29.52 61.3,29.64 60.91,29.56 60.79,29.39 52.8,27.79 51.77,26.76 36.5,23.71 25.66,12.87 25.45,12.87 25.17,12.58 25.17,12.37 24.88,12.09 24.68,12.09 24.39,11.8 24.39,11.6 24.11,11.31 23.9,11.31 23.62,11.03 23.62,10.82 23.33,10.54 22.59,6.84 22.37,6.62 21.89,6.62 v1(21.52,6.99)
  BOTTOM w0.13: J2.9 23.52,3.99 23.28,4.24 23.28,4.66 22.9,5.04 22.9,6.44 22.54,6.8 21.71,6.8 v1(21.52,6.99)
PE_CPU1_1B_TX_6_DP: length 72.7
  L6 w0.135: J4.B54 68.45,40.55 68.51,40.37 68.68,40.29 68.98,39.98 68.98,36.28 67.98,35.28 67.98,32.45 67.06,31.52 65.61,31.23 64.16,29.78 52.93,27.53 51.91,26.51 36.64,23.45 23.59,10.4 22.85,6.7 22.48,6.34 21.89,6.34 v1(21.52,5.97)
  BOTTOM w0.13: v1(21.52,5.97) 21.52,6.35 21.67,6.49 22.41,6.49 22.59,6.31 22.59,6.04 22.42,5.86 22.42,5.47 22.59,5.3 22.59,4.92 22.97,4.53 22.97,4.24 22.72,3.99 J2.11
PE_CPU1_1B_TX_7_DN: length 74
  L6 w0.135: v1(23.93,6.99) 24.29,6.62 24.77,6.62 24.99,6.84 25.74,10.59 26.03,10.88 26.03,11.08 26.31,11.37 26.52,11.37 26.8,11.65 26.8,11.86 27.09,12.14 27.29,12.14 27.58,12.43 27.58,12.63 27.86,12.92 28.07,12.92 37.92,22.77 52.35,25.65 53.38,26.68 64.63,28.93 65.27,29.57 65.27,29.77 65.55,30.06 65.76,30.06 66.04,30.34 67.64,30.66 67.76,30.83 68.15,30.91 68.32,30.8 68.72,30.88 68.83,31.05 69.23,31.13 69.4,31.01 69.79,31.09 70.08,31.38 70.08,31.58 70.37,31.87 70.57,31.87 71.7,33 71.7,35.39 72.7,36.39 72.7,39.88 72.52,40.06 72.39,40.13 72.21,40.07 J4.B51
  BOTTOM w0.13: J2.3 25.92,3.99 25.93,3.99 25.68,4.24 25.68,4.66 25.3,5.04 25.3,6.44 24.94,6.8 24.11,6.8 v1(23.93,6.99)
PE_CPU1_1B_TX_7_DP: length 74
  L6 w0.135: v1(23.93,5.97) 24.29,6.34 24.88,6.34 25.25,6.7 26,10.45 38.05,22.51 52.49,25.4 53.52,26.42 64.77,28.67 66.18,30.08 69.93,30.83 71.98,32.89 71.98,35.28 72.98,36.28 72.98,39.99 72.68,40.29 72.51,40.38 72.51,40.38 72.45,40.56 J4.B50
  BOTTOM w0.13: J2.5 25.12,3.99 25.37,4.24 25.37,4.53 24.99,4.92 24.99,5.3 24.82,5.47 24.82,5.86 24.99,6.04 24.99,6.31 24.81,6.49 24.07,6.49 23.93,6.35 v1(23.93,5.97)
PE_CPU1_1C_RX_8_DN: length 61.8
  TOP w0.13: v1(75.33,32.88) 75.69,32.53 75.69,32.08 75.56,31.47 74.97,30.87 66.63,29.2 65.27,27.84 53.97,25.58 53.14,24.75 45.08,23.14 43.69,21.75 43.69,21.05 42.75,19.17 42.75,16.36 43.69,14.48 43.69,13.73 43.54,13 39.61,9.07 38.78,4.88 38.78,4.24 38.53,3.99 J1.198
  BOTTOM w0.13: v1(75.33,32.88) 75.69,33.24 75.69,33.68 75.51,33.85 75.51,34.24 75.69,34.42 75.69,35.57 75.6,35.66 75.44,35.74 75.26,35.68 J4.A48
PE_CPU1_1C_RX_8_DP: length 61.7
  TOP w0.13: v1(76.35,32.88) 75.99,32.53 75.99,32.05 75.84,31.32 75.12,30.59 66.78,28.92 65.42,27.56 54.12,25.3 53.29,24.47 45.23,22.86 43.99,21.63 43.99,20.98 43.05,19.1 43.05,16.43 43.99,14.55 43.99,13.7 43.82,12.85 39.9,8.92 39.08,4.85 39.08,4.24 39.33,3.99 J1.196
  BOTTOM w0.13: J4.A47 75.51,36.18 75.57,36.01 75.78,35.91 75.99,35.7 75.99,33.24 v1(76.35,32.88)
PE_CPU1_1C_RX_9_DN: length 62.8
  TOP w0.13: v1(79.33,32.88) 79.69,32.52 79.69,32.11 79.58,31.56 78.32,30.3 67.24,28.08 65.9,26.74 54.69,24.5 53.85,23.66 48.55,22.6 47.69,21.74 47.69,21.05 46.75,19.17 46.75,16.36 47.69,14.48 47.69,13.72 47.07,13.1 46.17,12.92 41.94,8.69 41.18,4.88 41.18,4.24 40.93,3.99 J1.192
  BOTTOM w0.13: J4.A44 79.26,35.68 79.44,35.74 79.6,35.66 79.69,35.57 79.69,34.42 79.51,34.24 79.51,33.85 79.69,33.68 79.69,33.24 v1(79.33,32.88)
PE_CPU1_1C_RX_9_DP: length 62.8
  TOP w0.13: J1.190 41.73,3.99 41.48,4.24 41.48,4.85 42.22,8.54 46.32,12.64 47.22,12.82 47.99,13.59 47.99,14.55 47.05,16.43 47.05,19.1 47.99,20.98 47.99,21.61 48.7,22.32 54,23.37 54.84,24.21 66.05,26.46 67.39,27.8 78.47,30.01 79.86,31.41 80,32.08 80,32.53 v1(80.35,32.88)
  BOTTOM w0.13: v1(80.35,32.88) 79.99,33.24 79.99,35.7 79.78,35.91 79.57,36.01 79.51,36.18 J4.A43
PE_CPU1_1C_RX_10_DN: length 64.2
  TOP w0.13: J1.186 43.33,3.99 43.58,4.24 43.58,4.88 44.28,8.42 47.84,11.97 50.4,12.49 51.69,13.78 51.69,14.48 50.75,16.36 50.75,19.17 51.69,21.05 51.69,21.65 52.12,22.09 54.5,22.56 55.34,23.4 66.49,25.64 67.81,26.95 81.84,29.76 83.56,31.48 83.69,32.09 83.69,32.53 v1(83.33,32.88)
  BOTTOM w0.13: v1(83.33,32.88) 83.69,33.24 83.69,33.68 83.51,33.85 83.51,34.24 83.69,34.42 83.69,35.57 83.6,35.66 83.44,35.74 83.26,35.68 J4.A40
PE_CPU1_1C_RX_10_DP: length 64.1
  TOP w0.13: v1(84.35,32.88) 83.99,32.53 83.99,32.06 83.84,31.33 81.99,29.47 67.96,26.67 66.64,25.35 55.49,23.12 54.65,22.28 52.27,21.8 51.99,21.52 51.99,20.98 51.05,19.1 51.05,16.43 51.99,14.55 51.99,13.65 50.55,12.2 47.99,11.69 44.56,8.27 43.88,4.85 43.88,4.24 44.13,3.99 J1.184
  BOTTOM w0.13: v1(84.35,32.88) 83.99,33.24 83.99,35.7 83.78,35.91 83.57,36.01 83.51,36.18 J4.A39
PE_CPU1_1C_RX_11_DN: length 65.7
  TOP w0.13: J1.180 45.73,3.99 45.98,4.24 45.98,4.88 46.68,8.38 48.93,10.64 50.67,10.98 52.38,12.69 55.2,13.25 55.69,13.74 55.69,14.48 54.75,16.36 54.75,19.17 55.69,21.05 55.69,21.71 56.32,22.34 67.06,24.49 68.4,25.82 85.34,29.21 87.62,31.49 87.7,32.32 87.7,32.51 v1(87.33,32.88)
  BOTTOM w0.13: v1(87.33,32.88) 87.69,33.24 87.69,33.68 87.51,33.85 87.51,34.24 87.69,34.42 87.69,35.57 87.6,35.66 87.44,35.74 87.26,35.68 J4.A36
